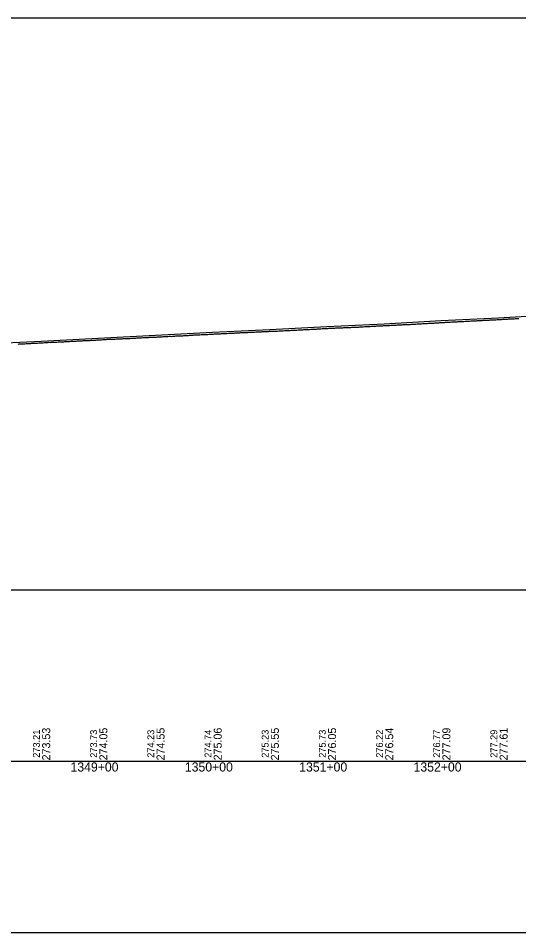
# Model space of a CAD drawing. Extents: x -3627 to 47473, y 2850 to 4350.
# Drawn here: x 22207 to 22645, y 2850 to 3650 of the extents above; entities that cross this region are included whole.
import ezdxf

# ---------------------------------------------------------------- set-up
doc = ezdxf.new("R2010")
doc.units = 0
for name, color, linetype in [('RD_DDB_Profile_EX', 7, 'Continuous'), ('RD_DDB_Profile_PR', 7, 'Continuous'), ('RD_DDB_StaTX', 7, 'Continuous'), ('RD_DDB_StripGrade', 7, 'Continuous'), ('RD_GPK_Profile_Cell', 7, 'Continuous'), ('RD_SHT_ShtClip', 7, 'Continuous')]:
    doc.layers.add(name, color=color, linetype=linetype)

msp = doc.modelspace()

# ---------------------------------------------------------------- linework, layer by layer
at = {"layer": 'RD_DDB_Profile_EX'}
for points in [[(22521.137346, 3380.865255), (22522.139813, 3380.906465), (22523.136138, 3380.9197), (22524.140195, 3380.92109), (22525.137306, 3381.00192), (22526.138985, 3381.036865), (22527.136337, 3381.09394), (22528.139604, 3381.133155), (22529.141286, 3381.137225), (22530.138746, 3381.20682), (22531.135179, 3381.33754), (22532.139577, 3381.345825), (22533.141358, 3381.41912), (22534.137791, 3381.46915), (22535.135252, 3381.443585), (22536.138628, 3381.488795), (22537.14144, 3381.59286), (22538.13798, 3381.63607), (22539.135554, 3381.679505), (22540.139031, 3381.78729), (22541.135571, 3381.77406), (22542.133141, 3381.82398), (22543.141959, 3381.935545), (22544.139535, 3381.99847), (22545.136085, 3382.048145), (22546.139671, 3382.09254), (22547.137353, 3382.13563), (22548.134002, 3382.17844), (22549.143954, 3382.1835), (22550.1406, 3382.22625), (22551.137247, 3382.28876), (22552.14187, 3382.383335), (22553.138526, 3382.445805), (22554.136336, 3382.538465), (22555.138412, 3382.52821), (22556.143144, 3382.572335), (22557.139899, 3382.634735), (22558.136655, 3382.740505), (22559.141387, 3382.77494), (22560.138142, 3382.8309), (22561.141294, 3382.928315), (22562.145041, 3382.98534), (22563.141901, 3382.986025), (22564.139613, 3383.034345), (22565.144198, 3383.105035), (22566.141062, 3383.153865), (22567.144055, 3383.185845), (22568.141801, 3383.227005), (22569.146389, 3383.312345), (22570.143368, 3383.38237), (22571.141246, 3383.387705), (22572.145932, 3383.451845), (22573.142915, 3383.5652), (22574.147598, 3383.60732), (22575.147043, 3383.694205), (22576.144941, 3383.79974), (22577.148724, 3383.87184), (22578.141499, 3383.879305), (22579.146302, 3383.913705), (22580.145852, 3383.972365), (22581.142968, 3384.035735), (22582.147771, 3384.08506), (22583.147322, 3384.12873), (22584.144442, 3384.177215), (22585.149258, 3384.23402), (22586.148929, 3384.292395), (22587.147112, 3384.39046), (22588.151093, 3384.43987), (22589.142825, 3384.44711), (22590.147747, 3384.488555), (22591.147427, 3384.581735), (22592.144678, 3384.63773), (22593.149612, 3384.63678), (22594.149419, 3384.68736), (22595.146796, 3384.743285), (22596.151838, 3384.857945), (22597.151655, 3384.858435), (22598.150026, 3384.91447), (22599.148856, 3385.007275), (22600.14652, 3385.048085), (22601.152129, 3385.089945), (22602.150365, 3385.149325), (22603.14815, 3385.205865), (22604.146392, 3385.29923), (22605.146878, 3385.308345), (22606.150364, 3385.35814), (22607.149604, 3385.45132), (22608.149116, 3385.445105), (22609.148368, 3385.53082), (22610.146784, 3385.58213), (22611.146152, 3385.633105), (22612.151976, 3385.69006), (22613.14366, 3385.697865), (22614.143024, 3385.78362), (22615.142652, 3385.785105), (22616.142015, 3385.87862), (22617.140474, 3385.929935), (22618.139965, 3385.98068), (22619.144989, 3386.03005), (22620.144483, 3386.088155), (22621.143977, 3386.102245)], [(22621.143977, 3386.102245), (22622.142572, 3386.17533), (22623.143223, 3386.21907), (22624.141827, 3386.263035), (22625.141337, 3386.321), (22626.139681, 3386.376045), (22627.139298, 3386.426545), (22628.138027, 3386.477375), (22629.137646, 3386.520705), (22630.138404, 3386.61429), (22631.137142, 3386.658075), (22632.142045, 3386.69926), (22633.141938, 3386.74329), (22634.141681, 3386.83645), (22635.140549, 3386.87262), (22636.140293, 3386.92286), (22637.140294, 3386.96658), (22638.140038, 3387.03092), (22639.137338, 3387.121225), (22640.138221, 3387.121665), (22641.1371, 3387.1651), (22642.136965, 3387.25084), (22643.137089, 3387.31558), (22644.136955, 3387.35845), (22645.141209, 3387.399455)], [(22421.1508, 3375.88232), (22422.145027, 3375.926155), (22423.151535, 3375.888525), (22424.145763, 3375.938785), (22425.14668, 3376.033425), (22426.146381, 3376.111775), (22427.147613, 3376.156825), (22428.148845, 3376.183925), (22429.147521, 3376.188025), (22430.14876, 3376.23288), (22431.143081, 3376.32643), (22432.149461, 3376.375045), (22433.143799, 3376.412035), (22434.150501, 3376.4108), (22435.150807, 3376.46823), (22436.145237, 3376.530905), (22437.146574, 3376.57548), (22438.14791, 3376.62014), (22439.149019, 3376.7079), (22440.143437, 3376.763955), (22441.144777, 3376.81509), (22442.145202, 3376.822065), (22443.146639, 3376.885525), (22444.148076, 3376.936275), (22445.149513, 3376.98703), (22446.143789, 3377.035915), (22447.139814, 3377.082645), (22448.141244, 3377.17109), (22449.141709, 3377.240135), (22450.143245, 3377.2406), (22451.144782, 3377.29106), (22452.138384, 3377.339965), (22453.140893, 3377.39062), (22454.141672, 3377.447485), (22455.143208, 3377.497925), (22456.143996, 3377.542605), (22457.145543, 3377.599075), (22458.146441, 3377.643505), (22459.135668, 3377.73253), (22460.13657, 3377.759175), (22461.139155, 3377.809605), (22462.14006, 3377.83983), (22463.141699, 3377.88408), (22464.14261, 3377.978665), (22465.13726, 3378.02136), (22466.138269, 3378.065605), (22467.139279, 3378.109865), (22468.141021, 3378.10971), (22469.142032, 3378.21586), (22470.144719, 3378.236235), (22471.140307, 3378.2836), (22472.13504, 3378.378755), (22473.136063, 3378.473015), (22474.137909, 3378.478455), (22475.139025, 3378.5224), (22476.140868, 3378.615995), (22477.141982, 3378.65991), (22478.14477, 3378.72153), (22479.133454, 3378.79009), (22480.135301, 3378.78373), (22481.136423, 3378.8098), (22482.137638, 3378.847385), (22483.139583, 3378.8905), (22484.14079, 3379.00196), (22485.142732, 3379.04506), (22486.137902, 3379.073495), (22487.139849, 3379.12273), (22488.135646, 3379.21255), (22489.137601, 3379.249555), (22490.138902, 3379.2926), (22491.140948, 3379.297475), (22492.142238, 3379.34046), (22493.144279, 3379.445395), (22494.138584, 3379.449185), (22495.140627, 3379.460125), (22496.141893, 3379.4655), (22497.138591, 3379.529655), (22498.141746, 3379.57823), (22499.143116, 3379.657855), (22500.145264, 3379.699625), (22501.139685, 3379.74631), (22502.141834, 3379.85101), (22503.143174, 3379.862835), (22504.145318, 3379.86113), (22505.141343, 3379.906075), (22506.145192, 3380.008665), (22507.142109, 3380.059455), (22508.143557, 3380.114285), (22509.140476, 3380.18463), (22510.136592, 3380.22923), (22511.145774, 3380.29842), (22512.141895, 3380.31239), (22513.138815, 3380.406535), (22514.135036, 3380.437935), (22515.145359, 3380.48751), (22516.142369, 3380.55072), (22517.138588, 3380.57064), (22518.135592, 3380.670945), (22519.144111, 3380.72071), (22520.141117, 3380.771015), (22521.137346, 3380.865255)], [(22221.270658, 3365.79556), (22222.273492, 3365.83728), (22223.274019, 3365.896135), (22224.272262, 3365.91708), (22225.273814, 3365.969215), (22226.275759, 3365.956665), (22227.271245, 3366.037185), (22228.268032, 3366.147705), (22229.269678, 3366.16976), (22230.273175, 3366.247995), (22231.268658, 3366.288545), (22232.2716, 3366.280095), (22233.272274, 3366.368305), (22234.269418, 3366.509125), (22235.272473, 3366.470245), (22236.273237, 3366.508425), (22237.270133, 3366.5981), (22238.271893, 3366.66983), (22239.270325, 3366.719915), (22240.271096, 3366.698345), (22241.268017, 3366.777915), (22242.26988, 3366.82901), (22243.272057, 3366.83556), (22244.269324, 3366.83594), (22245.271182, 3366.958075), (22246.268194, 3367.04741), (22247.270058, 3367.078925), (22248.267066, 3367.11833), (22249.2705, 3367.12992), (22250.267623, 3367.229085), (22251.274776, 3367.307935), (22252.271903, 3367.296935), (22253.269282, 3367.396925), (22254.271253, 3367.5282), (22255.268382, 3367.53697), (22256.270355, 3367.52802), (22257.267506, 3367.526955), (22258.271146, 3367.60832), (22259.268396, 3367.686895), (22260.270482, 3367.77797), (22261.267733, 3367.81671), (22262.269816, 3367.86741), (22263.268626, 3367.91657), (22264.270705, 3367.96727), (22265.26667, 3368.056425), (22266.269117, 3368.10773), (22267.266729, 3368.11718), (22268.269178, 3368.17849), (22269.266786, 3368.22789), (22270.269237, 3368.218895), (22271.265294, 3368.267755), (22272.27292, 3368.35719), (22273.265376, 3368.41866), (22274.262763, 3368.391535), (22275.26664, 3368.532), (22276.264027, 3368.58489), (22277.266393, 3368.62516), (22278.263796, 3368.678155), (22279.267675, 3368.72858), (22280.265078, 3368.791165), (22281.263735, 3368.862525), (22282.260261, 3368.96184), (22283.257538, 3368.97298), (22284.260311, 3369.064055), (22285.259045, 3369.144105), (22286.263043, 3369.184835), (22287.260552, 3369.19631), (22288.259252, 3369.248055), (22289.260669, 3369.298225), (22290.25949, 3369.30884), (22291.256126, 3369.30315), (22292.254934, 3369.395925), (22293.257875, 3369.42339), (22294.256672, 3369.434105), (22295.252917, 3369.51266), (22296.257037, 3369.585725), (22297.254691, 3369.62889), (22298.258932, 3369.678435), (22299.25034, 3369.761375), (22300.253219, 3369.787195), (22301.252115, 3369.829785), (22302.249858, 3369.864185), (22303.252753, 3369.863405), (22304.251637, 3369.956285), (22305.254558, 3369.96415), (22306.253563, 3370.048065), (22307.25793, 3370.11464), (22308.248097, 3370.164725), (22309.247093, 3370.198685), (22310.251464, 3370.223915), (22311.24912, 3370.333545), (22312.25349, 3370.4328), (22313.25117, 3370.475035), (22314.24916, 3370.48502), (22315.253656, 3370.542635), (22316.25144, 3370.59327), (22317.255935, 3370.642285), (22318.253719, 3370.65155), (22319.246465, 3370.69259), (22320.249838, 3370.72466), (22321.247642, 3370.816655)], [(22321.247642, 3370.816655), (22322.252269, 3370.88262), (22323.250177, 3370.91564), (22324.249417, 3370.942305), (22325.25405, 3371.041035), (22326.251956, 3371.0414), (22327.255449, 3371.131795), (22328.253356, 3371.158315), (22329.246279, 3371.198975), (22330.251049, 3371.238675), (22331.249081, 3371.288765), (22332.253849, 3371.3372), (22333.252084, 3371.396795), (22334.250319, 3371.479915), (22335.25393, 3371.569865), (22336.252169, 3371.629505), (22337.256954, 3371.6456), (22338.255323, 3371.687195), (22339.253692, 3371.78768), (22340.251099, 3371.785035), (22341.249467, 3371.74445), (22342.25436, 3371.91566), (22343.252728, 3372.01618), (22344.251096, 3372.034645), (22345.254835, 3372.07415), (22346.253335, 3372.174365), (22347.253013, 3372.224145), (22348.251512, 3372.283385), (22349.257704, 3372.294035), (22350.256204, 3372.308445), (22351.249334, 3372.328535), (22352.248992, 3372.419455), (22353.253839, 3372.512145), (22354.252471, 3372.538505), (22355.251103, 3372.56199), (22356.249735, 3372.620735), (22357.250455, 3372.673635), (22358.249088, 3372.714855), (22359.24772, 3372.8322), (22360.252702, 3372.842085), (22361.251359, 3372.933295), (22362.251261, 3372.98251), (22363.244614, 3373.00827), (22364.249739, 3373.009325), (22365.248506, 3373.08475), (22366.247274, 3373.167135), (22367.247174, 3373.21629), (22368.252296, 3373.23454), (22369.245666, 3373.294715), (22370.244572, 3373.344085), (22371.249844, 3373.43616), (22372.24987, 3373.443675), (22373.248776, 3373.493045), (22374.247682, 3373.54241), (22375.247523, 3373.54501), (22376.246428, 3373.644375), (22377.207059, 3373.718595), (22378.206251, 3373.75974), (22379.16391, 3373.8308), (22380.163107, 3373.897405), (22381.163722, 3373.950375), (22382.164338, 3373.986955), (22383.158332, 3373.988795), (22384.162859, 3374.04769), (22385.1635, 3374.142775), (22386.157564, 3374.1864), (22387.158274, 3374.216015), (22388.157548, 3374.23876), (22389.157033, 3374.299225), (22390.157756, 3374.3369), (22391.15702, 3374.443845), (22392.15774, 3374.49684), (22393.158469, 3374.557225), (22394.151375, 3374.55819), (22395.157475, 3374.61597), (22396.158305, 3374.61845), (22397.152358, 3374.7196), (22398.153172, 3374.77208), (22399.15252, 3374.83545), (22400.152213, 3374.87339), (22401.153049, 3374.92584), (22402.147153, 3374.96283), (22403.153406, 3375.040635), (22404.154327, 3375.0858), (22405.147332, 3375.11596), (22406.1536, 3375.16605), (22407.147683, 3375.22374), (22408.148601, 3375.23269), (22409.154893, 3375.326045), (22410.147998, 3375.37641), (22411.149026, 3375.358565), (22412.148545, 3375.476765), (22413.149569, 3375.528715), (22414.143714, 3375.52272), (22415.14907, 3375.57227), (22416.150104, 3375.6308), (22417.144247, 3375.63783), (22418.150753, 3375.730815), (22419.144986, 3375.768095), (22420.144292, 3375.819995), (22421.1508, 3375.88232)], [(22207.272836, 3364.95358), (22208.274458, 3365.152445), (22209.268644, 3365.09035), (22210.270376, 3365.178805), (22211.270806, 3365.22783), (22212.272532, 3365.27628), (22213.274513, 3365.285835), (22214.271086, 3365.396665), (22215.271507, 3365.44576), (22216.273235, 3365.4545), (22217.273663, 3365.5729), (22218.270359, 3365.5835), (22219.273445, 3365.6363), (22220.275282, 3365.71411), (22221.270658, 3365.79556)]]:
    msp.add_lwpolyline(points, dxfattribs=at)
at = {"layer": 'RD_DDB_Profile_PR'}
msp.add_lwpolyline([(22177.33, 3365.2075), (22227.33, 3367.6435), (22277.33, 3370.2285), (22327.33, 3372.734), (22377.33, 3375.3235), (22427.33, 3377.762), (22477.33, 3380.2715), (22527.33, 3382.7015), (22577.33, 3385.473), (22627.33, 3388.0365), (22677.33, 3390.839), (22727.33, 3393.8145), (22777.33, 3396.918), (22827.33, 3399.845), (22877.33, 3403.2125), (22927.33, 3406.593), (22977.33, 3409.826), (23027.33, 3412.87), (23077.33, 3415.9025), (23092.62, 3416.824774)], dxfattribs=at)
at = {"layer": 'RD_GPK_Profile_Cell'}
msp.add_line((1000, 3000), (46705.077602, 3000), dxfattribs=at)
at = {"layer": 'RD_SHT_ShtClip'}
for points in [[(21953.33, 3650), (21953.33, 3150), (23453.33, 3150), (23453.33, 3150), (23453.33, 3650), (23453.33, 3650)], [(21933.33, 3150), (23473.33, 3150), (23473.33, 2850), (21933.33, 2850)]]:
    msp.add_lwpolyline(points, close=True, dxfattribs=at)

# ---------------------------------------------------------------- texts
at = {"layer": 'RD_DDB_StaTX'}
for s, p in [('1349+00', (22253.125471, 2991)), ('1350+00', (22353.125471, 2991)), ('1351+00', (22453.125471, 2991)), ('1352+00', (22553.125471, 2991))]:
    msp.add_text(s, height=8, dxfattribs=at).set_placement(p)
at = {"layer": 'RD_DDB_StripGrade'}
for s, height, p in [('273.21', 6, (22226.33, 3003.073688)), ('273.53', 7, (22235.33, 3000.75)), ('273.73', 6, (22276.33, 3003.073688)), ('274.05', 7, (22285.33, 3000.75)), ('274.23', 6, (22326.33, 3003.073688)), ('274.55', 7, (22335.33, 3000.75)), ('274.74', 6, (22376.33, 3003.073688)), ('275.06', 7, (22385.33, 3000.75)), ('275.23', 6, (22426.33, 3003.073688)), ('275.55', 7, (22435.33, 3000.75)), ('275.73', 6, (22476.33, 3003.073688)), ('276.05', 7, (22485.33, 3000.75)), ('276.22', 6, (22526.33, 3003.073688)), ('276.54', 7, (22535.33, 3000.75)), ('276.77', 6, (22576.33, 3003.073688)), ('277.09', 7, (22585.33, 3000.75)), ('277.29', 6, (22626.33, 3003.073688)), ('277.61', 7, (22635.33, 3000.75))]:
    msp.add_text(s, height=height, rotation=90, dxfattribs=at).set_placement(p)

doc.saveas('drawing.dxf')
